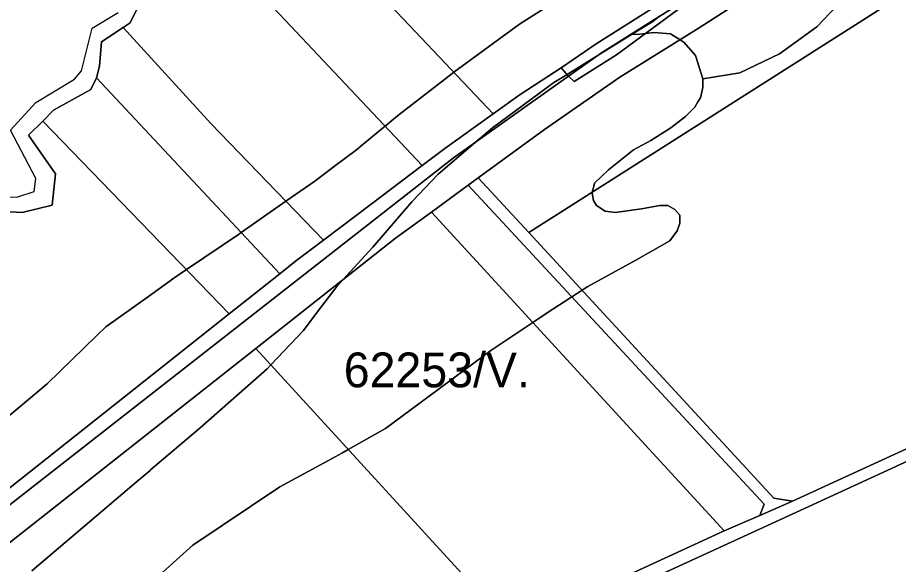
# Model space of a CAD drawing. Extents: x -522079 to -518792, y -1142400 to -1139961.
# Drawn here: x -521365.3 to -520985.3, y -1140523.8 to -1140287.7 of the extents above; entities that cross this region are included whole.
import ezdxf

# ---------------------------------------------------------------- set-up
doc = ezdxf.new("R2010")
doc.units = 0
for name, color, linetype in [('Hranice parcel', 7, 'Continuous'), ('Parcelní čísla', 7, 'Continuous'), ('Poz předměty', 7, 'Continuous'), ('Vnitřní kresba', 7, 'Continuous'), ('Značky bodu BP', 7, 'Continuous')]:
    doc.layers.add(name, color=color, linetype=linetype)

msp = doc.modelspace()

# ---------------------------------------------------------------- linework, layer by layer
at = {"layer": 'Hranice parcel'}
for points in [[(-521115.76, -1140299), (-521081.77, -1140277.41), (-521071.39, -1140271.24), (-521069.26, -1140274.95), (-521113.39, -1140302.86), (-521127.62, -1140312.94), (-521130.86, -1140309.33)], [(-521245.45, -1140392.88), (-521233.39, -1140383.74), (-521212.85, -1140368.17), (-521190.73, -1140351.49), (-521181.05, -1140344.19), (-521160.13, -1140329.24), (-521148.51, -1140320.94), (-521130.86, -1140309.33), (-521127.62, -1140312.94), (-521177.32, -1140348.18), (-521510.5, -1140608.85), (-521513.48, -1140605.69), (-521389.53, -1140507.12), (-521274.04, -1140415.55), (-521252.22, -1140398.25)], [(-521428.47, -1140683.93), (-521438.02, -1140688.47), (-521441.99, -1140684.63), (-521355.48, -1140644.9), (-521309.07, -1140623.96), (-521152, -1140551.52), (-521060.49, -1140509.3), (-521045.09, -1140502.65), (-521031.07, -1140496.4), (-520906.37, -1140439.12), (-520903.84, -1140443.54), (-521038.29, -1140505.39), (-521174.07, -1140567.72), (-521187.8, -1140573.75), (-521306.81, -1140628.37)]]:
    msp.add_lwpolyline(points, close=True, dxfattribs=at)
at = {"layer": 'Parcelní čísla'}
for points in [[(-521144.75, -1140380.49), (-521166.55, -1140356.84), (-521138.04, -1140336), (-521105.44, -1140313.39), (-521071.25, -1140292.13), (-521029.36, -1140265.01), (-520991.34, -1140239.5), (-520978.89, -1140274.79)], [(-521042, -1140261.25), (-521029.36, -1140265.01), (-521071.25, -1140292.13), (-521105.44, -1140313.39), (-521138.04, -1140336), (-521166.55, -1140356.84), (-521170.88, -1140360.01), (-521186.8, -1140371.65), (-521202.24, -1140382.94), (-521262.52, -1140430.5), (-521393.25, -1140533.65), (-521431, -1140563.44), (-521501.14, -1140618.78), (-521510.5, -1140608.85), (-521177.32, -1140348.18), (-521127.62, -1140312.94), (-521125.23, -1140315.3), (-521106.97, -1140303.78), (-521080.73, -1140284.42), (-521065.28, -1140272.43), (-521054.61, -1140266.48)], [(-521113.39, -1140302.86), (-521069.26, -1140274.95), (-521065.28, -1140272.43), (-521080.73, -1140284.42), (-521106.97, -1140303.78), (-521125.23, -1140315.3), (-521127.62, -1140312.94)], [(-520943.46, -1140405.56), (-520937.19, -1140417.44), (-520924.28, -1140409.64), (-520923.06, -1140411.9), (-520913.58, -1140428.33), (-520906.37, -1140439.12), (-521031.07, -1140496.4), (-521039.03, -1140495.22), (-521144.75, -1140380.49), (-520978.89, -1140274.79), (-520959.74, -1140329.07), (-520948.85, -1140357.77), (-520931.92, -1140395.43), (-520930.52, -1140398.04)], [(-521170.88, -1140360.01), (-521043.27, -1140497.72), (-521045.09, -1140502.65), (-521060.49, -1140509.3), (-521186.8, -1140371.65)], [(-521031.07, -1140496.4), (-521045.09, -1140502.65), (-521043.27, -1140497.72), (-521170.88, -1140360.01), (-521166.55, -1140356.84), (-521144.75, -1140380.49), (-521039.03, -1140495.22)], [(-521060.49, -1140509.3), (-521152, -1140551.52), (-521262.52, -1140430.5), (-521202.24, -1140382.94), (-521186.8, -1140371.65)], [(-521309.07, -1140623.96), (-521393.25, -1140533.65), (-521262.52, -1140430.5), (-521152, -1140551.52)], [(-521174.07, -1140567.72), (-521038.29, -1140505.39), (-520903.84, -1140443.54), (-520902.4, -1140445.74), (-520890.58, -1140462.46), (-520871.65, -1140486.28), (-520862.22, -1140497.87), (-521134.28, -1140622.71), (-521175.11, -1140573.76)]]:
    msp.add_lwpolyline(points, close=True, dxfattribs=at)
at = {"layer": 'Poz předměty'}
for points in [[(-521303.57, -1140232.09), (-521288.02, -1140193.37), (-521224.97, -1140260.52), (-521160.13, -1140329.24), (-521181.05, -1140344.19), (-521190.73, -1140351.49), (-521249.83, -1140288.83)], [(-521319.77, -1140291.98), (-521316.7, -1140289.98), (-521313.45, -1140283.14), (-521313.53, -1140260.28), (-521303.57, -1140232.09), (-521249.83, -1140288.83), (-521190.73, -1140351.49), (-521212.85, -1140368.17), (-521233.39, -1140383.74), (-521281.93, -1140333.33)], [(-521331.35, -1140313.68), (-521329.93, -1140308.65), (-521329.18, -1140298.1), (-521319.77, -1140291.98), (-521281.93, -1140333.33), (-521233.39, -1140383.74), (-521245.45, -1140392.88), (-521252.22, -1140398.25)], [(-521349.83, -1140327.64), (-521333.68, -1140318.76), (-521331.35, -1140313.68), (-521252.22, -1140398.25), (-521274.04, -1140415.55), (-521354.5, -1140332.33)], [(-521443.44, -1140442.21), (-521430.97, -1140433.67), (-521425.29, -1140415.18), (-521414.4, -1140412.25), (-521409.97, -1140408.74), (-521387.23, -1140382.25), (-521376.68, -1140371.11), (-521363.37, -1140371.78), (-521350.48, -1140368.68), (-521348.98, -1140355.15), (-521360.62, -1140338.49), (-521354.5, -1140332.33), (-521274.04, -1140415.55), (-521389.53, -1140507.12), (-521435.8, -1140458.35), (-521435.3, -1140455)]]:
    msp.add_lwpolyline(points, close=True, dxfattribs=at)
msp.add_lwpolyline([(-521081.77, -1140277.41), (-521115.76, -1140299), (-521130.86, -1140309.33), (-521148.51, -1140320.94), (-521160.13, -1140329.24), (-521224.97, -1140260.52)], dxfattribs=at)
at = {"layer": 'Vnitřní kresba'}
for points in [[(-521313.45, -1140283.14), (-521316.7, -1140289.98), (-521319.77, -1140291.98), (-521329.18, -1140298.1), (-521329.93, -1140308.65), (-521331.35, -1140313.68), (-521333.68, -1140318.76), (-521349.83, -1140327.64), (-521354.5, -1140332.33), (-521360.62, -1140338.49), (-521348.98, -1140355.15), (-521350.48, -1140368.68), (-521363.37, -1140371.78), (-521376.68, -1140371.11)], [(-521379.07, -1140365.7), (-521365.2, -1140365.12), (-521358.18, -1140362.8), (-521357.5, -1140357.21), (-521368.43, -1140336.25), (-521357.43, -1140324.38), (-521340.77, -1140314.23), (-521337.76, -1140310.68), (-521333.16, -1140292.26), (-521321.89, -1140285.5)]]:
    msp.add_lwpolyline(points, dxfattribs=at)
at = {"layer": 'Značky bodu BP'}
for points in [[(-521311.93, -1140535.49), (-521296.83, -1140521.82), (-521289.79, -1140515.44), (-521252.24, -1140490.24), (-521229.55, -1140478.05), (-521225.41, -1140475.7), (-521222.66, -1140474.14), (-521206.6, -1140465.04), (-521176.08, -1140442.55), (-521161.22, -1140431.44), (-521143.07, -1140419.31), (-521136.91, -1140415.19), (-521126.19, -1140408.24), (-521121.8, -1140405.39), (-521120.88, -1140404.8), (-521119.35, -1140403.81), (-521098.56, -1140392.43), (-521083.97, -1140384.03), (-521080.73, -1140379.69), (-521079.65, -1140376.44), (-521079.65, -1140372.92), (-521081.81, -1140370.48), (-521084.78, -1140368.85), (-521088.29, -1140368.85), (-521096.13, -1140370.21), (-521107.47, -1140371.83), (-521111.79, -1140371.29), (-521115.57, -1140368.85), (-521116.92, -1140366.69), (-521117.46, -1140363.44), (-521117.4, -1140363.19), (-521117.37, -1140363.04), (-521116.86, -1140361), (-521116.38, -1140359.1), (-521110.44, -1140353.41), (-521099.64, -1140344.74), (-521092.08, -1140340.68), (-521083.43, -1140335.26), (-521077.22, -1140330.38), (-521073.17, -1140326.32), (-521071.78, -1140324), (-521070.74, -1140322.25), (-521069.66, -1140317.92), (-521069.66, -1140314.12), (-521053.67, -1140311.59), (-521036.58, -1140303.28), (-521020.52, -1140291.59), (-521006.02, -1140276.26)], [(-521006.02, -1140276.26), (-521020.52, -1140291.59), (-521036.58, -1140303.28), (-521053.67, -1140311.59), (-521069.66, -1140314.12), (-521072.9, -1140304.1), (-521077.76, -1140298.41), (-521079.53, -1140297.28), (-521083.7, -1140294.61), (-521090.72, -1140294.07), (-521094.48, -1140294.57), (-521095.55, -1140294.7), (-521096.94, -1140294.88), (-521100.44, -1140295.01), (-521091.26, -1140289.33), (-521088.2, -1140286.93)], [(-521130.6, -1140278.79), (-521148.82, -1140290.47), (-521177.07, -1140311.28), (-521181.2, -1140314.33), (-521201.45, -1140330.07), (-521206.77, -1140334.49), (-521207.36, -1140334.98), (-521217.11, -1140343.09), (-521218.18, -1140343.98), (-521219.16, -1140344.78), (-521228.64, -1140351.89), (-521237.12, -1140358.24), (-521249.54, -1140366.96), (-521268.83, -1140380.5), (-521270.02, -1140381.34), (-521292.47, -1140396.49), (-521297.85, -1140400.12), (-521308.89, -1140408.04), (-521327.2, -1140421.19), (-521331.09, -1140424.97), (-521352.5, -1140445.81), (-521373.25, -1140463.07)], [(-521373.25, -1140463.07), (-521352.5, -1140445.81), (-521331.09, -1140424.97), (-521327.2, -1140421.19), (-521308.89, -1140408.04), (-521297.85, -1140400.12), (-521292.47, -1140396.49), (-521270.02, -1140381.34), (-521268.83, -1140380.5), (-521249.54, -1140366.96), (-521237.12, -1140358.24), (-521228.64, -1140351.89), (-521219.16, -1140344.78), (-521218.18, -1140343.98), (-521217.11, -1140343.09), (-521207.36, -1140334.98), (-521206.77, -1140334.49), (-521201.45, -1140330.07), (-521181.2, -1140314.33), (-521177.07, -1140311.28), (-521148.82, -1140290.47), (-521130.6, -1140278.79)], [(-521379.07, -1140365.7), (-521365.2, -1140365.12), (-521358.18, -1140362.8), (-521357.5, -1140357.21), (-521368.43, -1140336.25), (-521357.43, -1140324.38), (-521340.77, -1140314.23), (-521337.76, -1140310.68), (-521333.16, -1140292.26), (-521321.89, -1140285.5)], [(-521088.2, -1140286.93), (-521091.26, -1140289.33), (-521100.44, -1140295.01), (-521115.27, -1140304.19), (-521128.26, -1140312.23), (-521133.94, -1140315.75), (-521160.41, -1140335.26), (-521166.87, -1140340.77), (-521183.91, -1140355.31), (-521195.25, -1140367.23), (-521212, -1140386.74), (-521224.97, -1140400.87), (-521227.66, -1140403.81), (-521236.04, -1140414.91), (-521241.98, -1140422.77), (-521256.03, -1140437.6), (-521257.64, -1140439.3), (-521286.54, -1140464.77), (-521307.94, -1140482.96), (-521308.2, -1140483.19), (-521314.13, -1140488.23), (-521359.2, -1140526.55)], [(-521359.2, -1140526.55), (-521314.13, -1140488.23), (-521308.2, -1140483.19), (-521307.94, -1140482.96), (-521286.54, -1140464.77), (-521257.64, -1140439.3), (-521256.03, -1140437.6), (-521241.98, -1140422.77), (-521236.04, -1140414.91), (-521227.66, -1140403.81), (-521224.97, -1140400.87), (-521212, -1140386.74), (-521195.25, -1140367.23), (-521183.91, -1140355.31), (-521166.87, -1140340.77), (-521160.41, -1140335.26), (-521133.94, -1140315.75), (-521128.26, -1140312.23), (-521115.27, -1140304.19), (-521100.44, -1140295.01), (-521096.94, -1140294.88), (-521095.55, -1140294.7), (-521094.48, -1140294.57), (-521090.72, -1140294.07), (-521083.7, -1140294.61), (-521079.53, -1140297.28), (-521077.76, -1140298.41), (-521072.9, -1140304.1), (-521069.66, -1140314.12), (-521069.66, -1140317.92), (-521070.74, -1140322.25), (-521071.78, -1140324), (-521073.17, -1140326.32), (-521077.22, -1140330.38), (-521083.43, -1140335.26), (-521092.08, -1140340.68), (-521099.64, -1140344.74), (-521110.44, -1140353.41), (-521116.38, -1140359.1), (-521116.86, -1140361), (-521117.37, -1140363.04), (-521117.4, -1140363.19), (-521117.46, -1140363.44), (-521116.92, -1140366.69), (-521115.57, -1140368.85), (-521111.79, -1140371.29), (-521107.47, -1140371.83), (-521096.13, -1140370.21), (-521088.29, -1140368.85), (-521084.78, -1140368.85), (-521081.81, -1140370.48), (-521079.65, -1140372.92), (-521079.65, -1140376.44), (-521080.73, -1140379.69), (-521083.97, -1140384.03), (-521098.56, -1140392.43), (-521119.35, -1140403.81), (-521120.88, -1140404.8), (-521121.8, -1140405.39), (-521126.19, -1140408.24), (-521136.91, -1140415.19), (-521143.07, -1140419.31), (-521161.22, -1140431.44), (-521176.08, -1140442.55), (-521206.6, -1140465.04), (-521222.66, -1140474.14), (-521225.41, -1140475.7), (-521229.55, -1140478.05), (-521252.24, -1140490.24), (-521289.79, -1140515.44), (-521296.83, -1140521.82), (-521311.93, -1140535.49)]]:
    msp.add_lwpolyline(points, dxfattribs=at)

# ---------------------------------------------------------------- texts
msp.add_text('62253/V.', height=15, dxfattribs=at).set_placement((-521224.61, -1140447.29))

doc.saveas('drawing.dxf')
